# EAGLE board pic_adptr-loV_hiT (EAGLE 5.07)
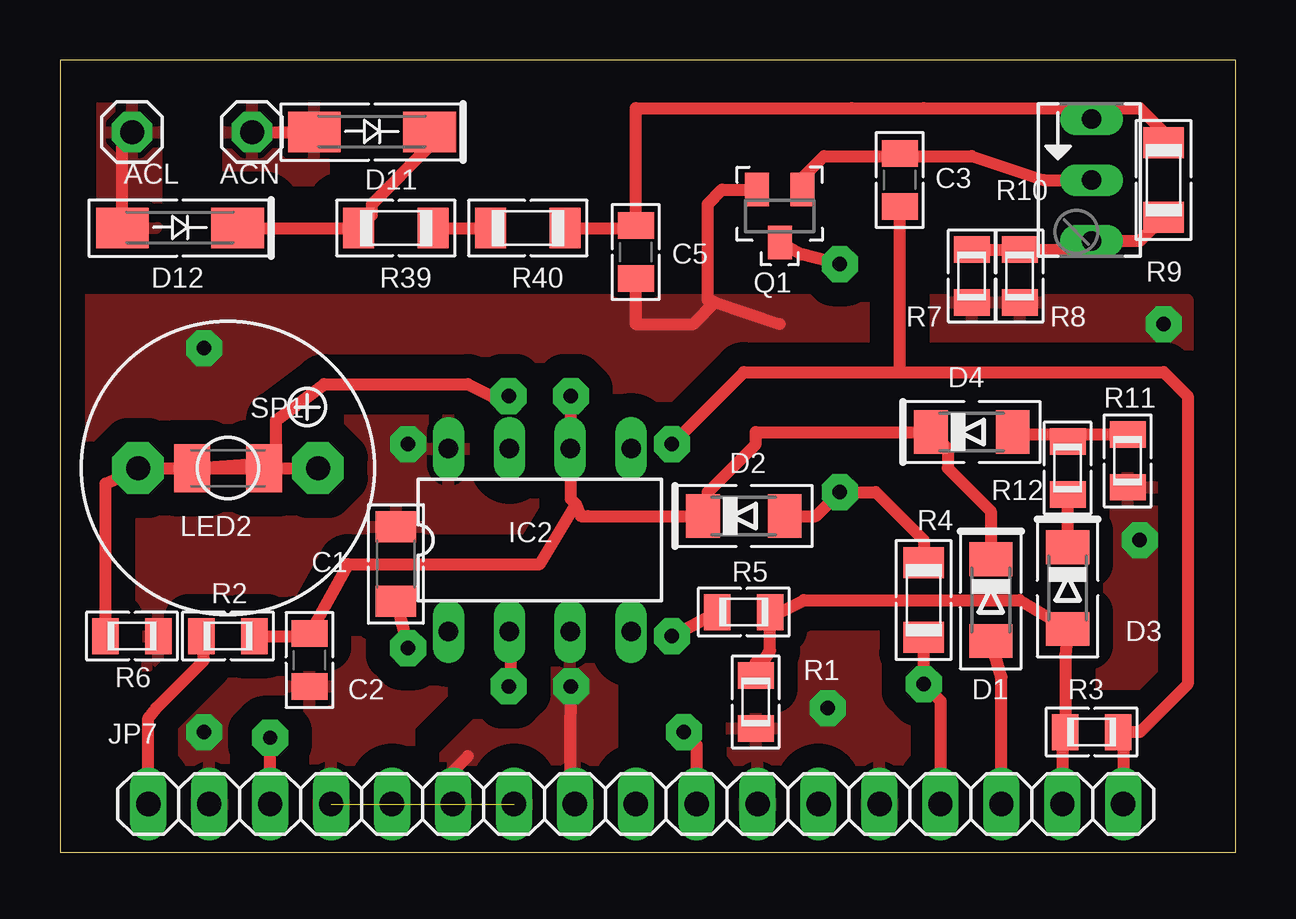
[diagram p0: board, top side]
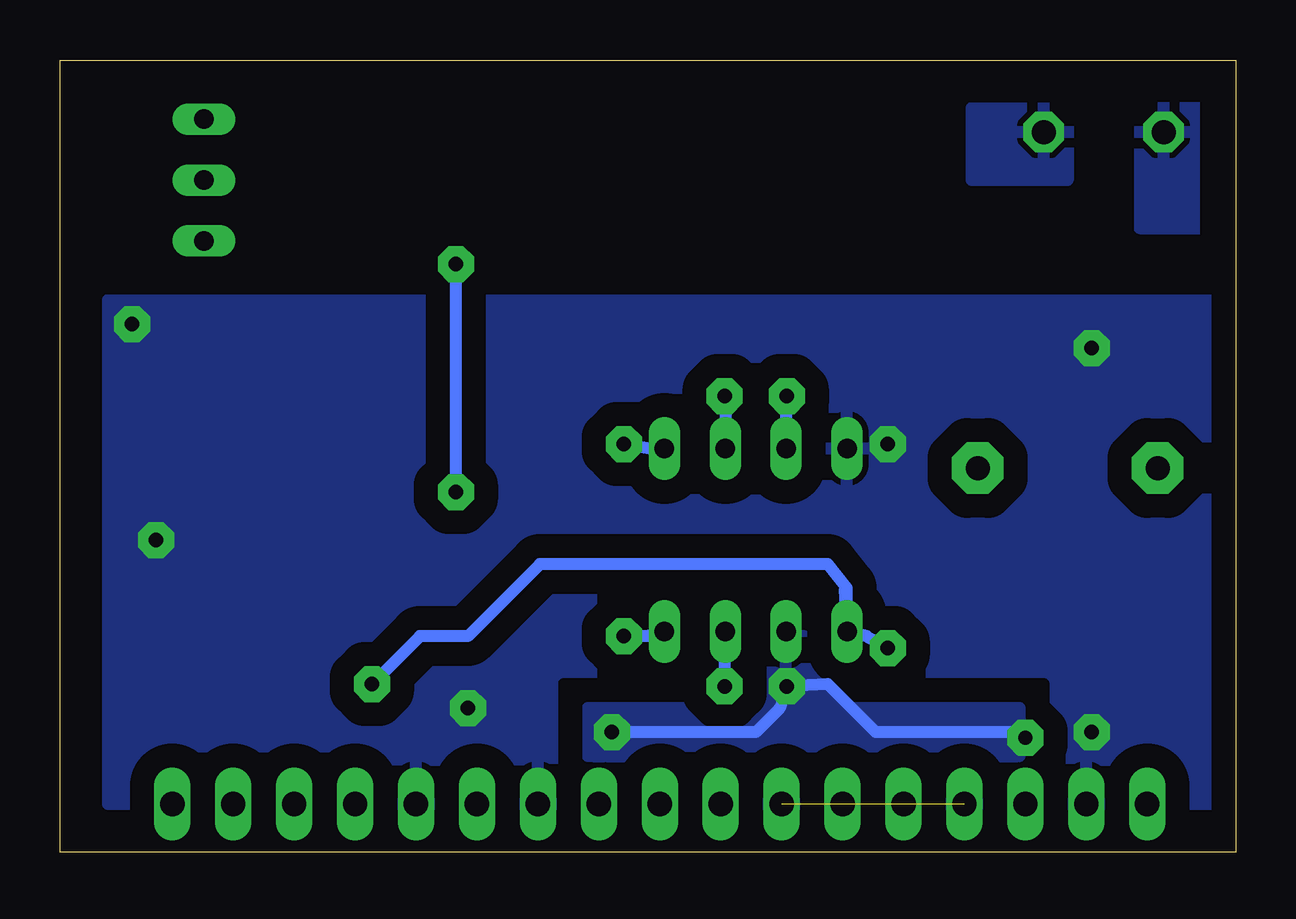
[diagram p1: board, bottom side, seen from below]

Size 49 x 33 mm. Coordinates in mm from the lower left corner, seen from the top.
Outline: 0,0 49,0 49,33 0,33 0,0
Copper layers (1*16): Top 0.035mm / dielectric 1.5mm / Bottom 0.035mm
Design rules "default *": minimum track width 10mil, minimum drill 20mil, track to track 8mil, track to pad 8mil, pad to pad 8mil, via to via 8mil, smd to smd 8mil, copper to edge 40mil, drill to drill 8mil, minimum pad ring 10mil, minimum via ring 8mil, stop-mask expansion 4mil, vias tented up to drill 0mil, thermal gap 10mil

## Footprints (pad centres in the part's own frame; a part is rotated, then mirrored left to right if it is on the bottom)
1X01 = drill 1 pad 1.676 octagon: 1 0,0
C1206 = smd 1.3 x 1.7: 1 -1.55,0; 2 1.55,0
C0805 = smd 1.1 x 1.5: 1 -1.1,0; 2 1.1,0
MINIMELF = smd 1.4 x 1.8: A 1.7,0; C -1.7,0
SMA-DO214AC = smd 2.2 x 1.7: A 2.4,0; K -2.4,0
DIL8 = drill 0.8 long: 1 -3.81,-3.81; 2 -1.27,-3.81; 3 1.27,-3.81; 4 3.81,-3.81; 5 3.81,3.81; 6 1.27,3.81; 7 -1.27,3.81; 8 -3.81,3.81
1X17 = drill 1.016 long: 1 -20.32,0; 2 -17.78,0; 3 -15.24,0; 4 -12.7,0; 5 -10.16,0; 6 -7.62,0; 7 -5.08,0; 8 -2.54,0; 9 0,0; 10 2.54,0; 11 5.08,0; 12 7.62,0; 13 10.16,0; 14 12.7,0; 15 15.24,0; 16 17.78,0; 17 20.32,0
C1206K = smd 1.5 x 2: 1 -1.5,0; 2 1.5,0
SOT23 = smd 1 x 1.4: 1 -0.95,-1.1; 2 0.95,-1.1; 3 0,1.1
R0805 = smd 1.1 x 1.5: 1 -1.1,0; 2 1.1,0
R1206 = smd 1.3 x 1.7: 1 -1.55,0; 2 1.55,0
B64Y = drill 0.813 long: A 2.54,0; E -2.54,0; S 0,0
KSS1202 = drill 1 pad 2.159 octagon: + 3.75,0; - -3.75,0

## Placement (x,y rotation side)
ACL  [1X01]  3,30 0 top
ACN  [1X01]  8,30 0 top
C1  [C1206]  14,12 90 top
C2  22p  [C0805]  10.4,8 270 top
C3  10n  [C0805]  35,28 90 top
C5  10n  [C0805]  24,25 270 top
D1  [MINIMELF]  38.8,10.5 270 top
D2  [MINIMELF]  28.5,14 0 top
D3  [MINIMELF]  42,11 270 top
D4  [MINIMELF]  38,17.5 0 top
D11  M7  [SMA-DO214AC]  13,30 180 top
D12  M7  [SMA-DO214AC]  5,26 180 top
IC2  PIC12F675P  [DIL8]  20,13 0 top
JP7  [1X17]  24,2 0 top
LED2  [C1206K]  7,16 0 top
Q1  BC847ALT1SMD  [SOT23]  30,26.5 180 top
R1  [R0805]  29,6.25 90 top
R2  [R0805]  7,9 0 top
R3  [R0805]  43,5 0 top
R4  [R1206]  36,10.5 270 top
R5  [R0805]  28.5,10 0 top
R6  [R0805]  3,9 180 top
R7  [R0805]  38,24 90 top
R8  [R0805]  40,24 90 top
R9  [R1206]  46,28 90 top
R10  [B64Y]  43,28 270 top
R11  [R0805]  44.5,16.3 270 top
R12  [R0805]  42,16 90 top
R39  Rtop/2  [R1206]  14,26 180 top
R40  Rtop/2  [R1206]  19.5,26 180 top
SP1  KSS12017MM  [KSS1202]  7,16 0 top

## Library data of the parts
ACL ACN JP7 = pinhead
C1-C3 C5 R1-R9 R11 R12 = rcl
D1-D4 D11 D12 = diode
IC2 = microchip-5
LED2 R39 R40 = rcl-2
Q1 = transistor-npn
R10 = pot
SP1 = buzzer

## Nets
1HO2LO: IC2.3 JP7.6 JP7.8
1LO2HO: IC2.2 JP7.3 JP7.10
12V: JP7.12
ACL: ACL.1 D12.A
ACN: ACN.1 D11.A
BLACK: JP7.5
FAN: C3.1 IC2.5 JP7.17 R3.2
GND: C1.2 C2.2 C5.2 IC2.8 JP7.2 JP7.4 JP7.7 JP7.11 JP7.13 Q1.2 R1.1 R6.1 R7.1 R8.1 R11.2
GP1: C2.1 D1.C D2.C D4.C IC2.6 R2.2
IFB: JP7.1 R2.1
N$2: D11.K D12.K R39.2
N$3: IC2.4 R5.1
N$4: IC2.7 LED2.1 SP1.+
N$5: LED2.2 R6.2 SP1.-
N$6: R39.1 R40.2
N$7: D2.A Q1.3 R4.1
N$8: D3.C R12.1
N$9: D4.A R11.1 R12.2
N$12: R7.2 R8.2 R9.1 R10.A
N$13: C3.2 Q1.1 R10.S
N$19: C5.1 R9.2 R10.E R40.1
RED: JP7.9
TFB: D3.A JP7.16 R1.2 R3.1 R5.2
VDD: C1.1 IC2.1 JP7.14 R4.2
VFB: D1.A JP7.15

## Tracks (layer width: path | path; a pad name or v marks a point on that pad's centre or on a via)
1HO2LO  (via drill 0.6 pad 1.5)
  Top 0.5: v21.3,6.9 21.27,2.19 JP7.8 | 17,4 16,3 16,2.38 JP7.6
  Bottom 0.5: v21.3,6.9 IC2.3
  pour Top (isolate 1, rank 2): 20,8 23,8 23,1 21,1 21,3 18,3 18,2 17,1 15,1 15,3
1LO2HO  (via drill 0.6 pad 1.5)
  Top 0.5: JP7.3 v8.76,4.76 | JP7.10 26.54,4.46 v26,5 | v18.7,6.9 18.8,7.6 18.8,9.1
  Bottom 0.5: v8.76,4.76 9,5 15,5 16,6 17,7 v18.7,6.9 19,6 20,5 v26,5 | IC2.2 19,8.92 IC2.2
  pour Bottom (isolate 1): 19,9 20,8 20,7 21,6 27,6 27,4 9,4 9,6 16,6 17,7 17,8 18,9
ACL
  Top 0.5: D12.A 2.6,29.4 ACL.1
  pour Bottom (isolate 1.5): 1,31 4,31 4,26 1,26
  pour Top (isolate 1.5): 1,31 4,31 4,26 1,26
ACN
  Top 0.5: ACN.1 D11.A
  pour Bottom (isolate 1.5): 7,31 7,28 11,28 11,31
  pour Top (isolate 1.5): 7,31 7,28 11,28 11,31
FAN  (via drill 0.6 pad 1.5)
  Top 0.5: JP7.17 44.32,4.78 R3.2 45,5 47,7 47,19 46,20 35,20 | 35,20 28.5,20 v25.5,17 | 35,20 C3.1
  Bottom 0.5: IC2.5 24.41,16.81 v25.5,17
GND  (via drill 0.6 pad 1.5)  (1 unrouted)
  Top 0.5: 27.3,22.9 27,23 27,27 27.6,27.6 Q1.2 | 27.3,22.9 30,22 | C5.2 24,22 26.4,22 27.3,22.9
  other vias: 46,22 14.5,17 6,21 45,13 32,6 6,5
  pour Top (isolate 1, rank 3): 47,23 1,23 1,1 47,1
  pour Bottom (isolate 1, rank 3): 47,23 1,23 1,2 47,2
GP1  (via drill 0.6 pad 1.5)
  Top 0.5: 21.5,14.5 21.7,14 22,14 27,14 | 21.5,14.5 20,12 12,12 C2.1 10.3,9 R2.2 | v21.3,19 21.3,16.3 21.3,14.7 21.5,14.5 | 27,14 D2.C 27,14 | 39.2,12.2 39,12 D1.C 38.8,14.2 38,15 37,16 37,16.8 D4.C 36,17.5 29,17.5 29,17 27,15 27,14
  Bottom 0.5: IC2.6 21.27,18.77 v21.3,19
IFB
  Top 0.5: JP7.1 3.68,5.58 4,6 6,8 R2.1
N$2
  Top 0.5: D11.K 15.4,29.4 13,27 13,26.55 R39.2 D12.K
N$3  (via drill 0.6 pad 1.5)
  Top 0.5: v25.5,9 R5.1
  Bottom 0.5: v25.5,9 24.52,9 IC2.4
N$4  (via drill 0.6 pad 1.5)
  Top 0.5: v18.7,19 18.2,18.8 18,19 17,19.5 11,19.5 9,18 9,16.25 LED2.1 SP1.+
  Bottom 0.5: IC2.7 18.73,18.77 v18.7,19
N$5
  Top 0.5: LED2.2 SP1.- 1.9,15.35 R6.2
N$6
  Top 0.5: R39.1 17.45,26 R40.2
N$7  (via drill 0.6 pad 1.5)
  Top 0.5: Q1.3 30.9,24.9 v32.5,24.5 | D2.A 31.5,14 v32.5,15 34,15 36,13 R4.1
  Bottom 0.5: v32.5,15 v32.5,24.5
N$8
  Top 0.5: D3.C 42,12.9 R12.1
N$9
  Top 0.5: R11.1 42.1,17.4 42.02,17.4 | R12.2 42,17.39 42.02,17.4 | 42.02,17.4 39.8,17.4 D4.A
N$12
  Top 0.5: R7.2 R8.2 42.64,25.1 R10.A 45.01,25.46 R9.1
N$13
  Top 0.5: R10.S 41,28 38,29 34,29 | 34,29 31.85,29 30.95,28.1 Q1.1 | 34,29 34.9,29 C3.2
N$19
  Top 0.5: C5.1 23.95,26.5 | C5.1 24,28 24,31 33,31 36,31 42.54,31 R10.E 43.46,31 45,31 46,30 R9.2 | R40.1 23.9,26 C5.1
TFB
  Top 0.5: JP7.16 41.78,4.88 R3.1 41.9,8.2 D3.A 40,10.5 31,10.5 30,10 R5.2 29.6,8.4 R1.2 29,7.9
VDD  (via drill 0.6 pad 1.5)
  Top 0.5: C1.1 v14.5,8.5 | JP7.14 36.7,6.3 v36,7 R4.2
  Bottom 0.5: IC2.1 16.2,9.48 16.2,11 17,12 29,12 32,9 34,9 v36,7 35.7,7 | IC2.1 16.28,11 | v14.5,8.5 15.38,9 IC2.1
VFB
  Top 0.5: JP7.15 39.24,7.29 D1.A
